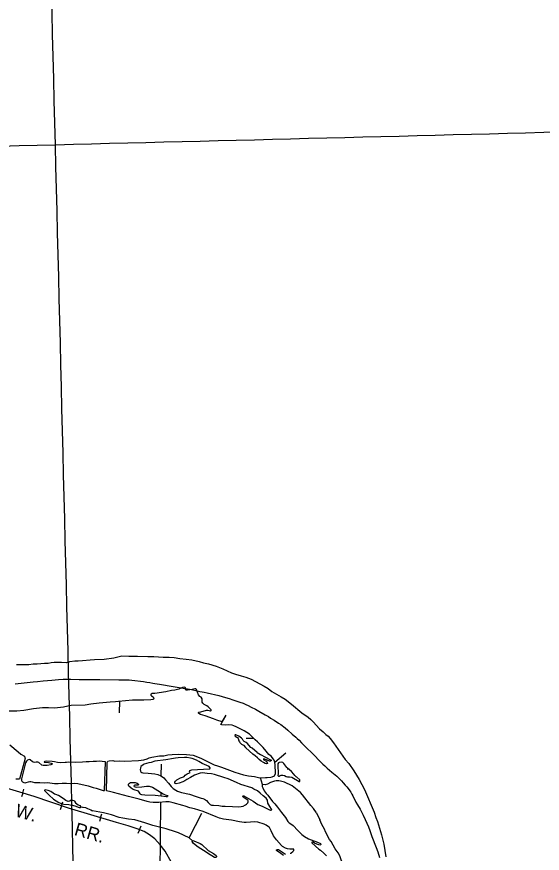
# Model space of a CAD drawing. Extents: x -19 to 366, y -4 to 359.
# Drawn here: x 141.56 to 144.78, y 204.19 to 209.31 of the extents above; entities that cross this region are included whole.
import ezdxf

# ---------------------------------------------------------------- set-up
doc = ezdxf.new("R2010")
doc.units = 0
for name, color, linetype in [('R_Alt Surface', 7, 'Continuous'), ('R_Axis Annot', 7, 'Continuous'), ('R_Border Prem', 7, 'Continuous'), ('R_Temp Easement', 7, 'Continuous'), ('R_Water Annot', 7, 'Continuous'), ('Sheet Fence', 7, 'Continuous')]:
    doc.layers.add(name, color=color, linetype=linetype)

msp = doc.modelspace()

# ---------------------------------------------------------------- linework, layer by layer
at = {"layer": 'R_Alt Surface'}
for points in [[(141.5515, 205.2236), (141.661, 205.2362), (141.6879, 205.2388), (141.7231, 205.242), (141.7768, 205.2467), (141.8179, 205.2499), (141.8458, 205.2525), (141.8589, 205.2525), (141.8926, 205.2523), (141.9431, 205.2504), (142.0193, 205.2496)], [(142.0193, 205.2496), (142.0693, 205.2496), (142.1869, 205.249), (142.2292, 205.2484), (142.2505, 205.2475), (142.2665, 205.246), (142.3385, 205.238), (142.3571, 205.2348), (142.3772, 205.2315), (142.3953, 205.2286), (142.4077, 205.2265), (142.4347, 205.2218), (142.5197, 205.2081), (142.5673, 205.1986), (142.6313, 205.1886), (142.6656, 205.1818), (142.6828, 205.1776), (142.6961, 205.1749), (142.7094, 205.1723), (142.7275, 205.1678), (142.7988, 205.1515), (142.8193, 205.1459), (142.8394, 205.1403), (142.8616, 205.1335), (142.8847, 205.1252), (142.9033, 205.1195), (142.927, 205.1115), (142.9475, 205.1047), (142.9652, 205.0976), (142.9791, 205.0917), (142.9975, 205.0819), (143.023, 205.0689), (143.0437, 205.0573), (143.0822, 205.0351), (143.1029, 205.0229), (143.1156, 205.0147), (143.1368, 205.0011), (143.1639, 204.9835), (143.1787, 204.974), (143.205, 204.9545), (143.2207, 204.9406), (143.2489, 204.9163), (143.2702, 204.8976), (143.2782, 204.8902), (143.2912, 204.8781), (143.306, 204.863), (143.3196, 204.8484), (143.3865, 204.7827), (143.412, 204.7569), (143.4241, 204.7444), (143.436, 204.732), (143.4475, 204.721), (143.4629, 204.7086), (143.4919, 204.6837), (143.5014, 204.6754), (143.5209, 204.6582), (143.5502, 204.6298), (143.5609, 204.6176), (143.5727, 204.604), (143.5822, 204.5933), (143.5908, 204.5833), (143.6015, 204.5699), (143.6077, 204.5599), (143.6136, 204.5495), (143.6189, 204.5376), (143.6388, 204.4994), (143.6485, 204.4828), (143.6642, 204.4562), (143.6826, 204.4203), (143.6941, 204.3945), (143.7045, 204.372), (143.7152, 204.3489), (143.724, 204.3261), (143.7368, 204.2897), (143.7619, 204.2212), (143.7717, 204.1949), (143.7829, 204.1608)]]:
    msp.add_lwpolyline(points, dxfattribs=at)
at = {"layer": 'R_Axis Annot'}
for points in [[(142.1899, 205.0458), (142.1925, 205.1185)], [(142.9669, 204.8907), (143.0126, 204.8917)], [(142.4463, 204.6598), (142.4472, 204.7328)], [(143.2202, 204.7076), (143.2202, 204.6985)], [(142.4449, 204.5364), (142.4451, 204.5585)], [(142.4392, 204.0642), (142.4444, 204.4985)]]:
    msp.add_lwpolyline(points, dxfattribs=at)
at = {"layer": 'R_Border Prem'}
for points in [[(141.8789, 205.3572), (141.8859, 205.3607), (141.9162, 205.3643), (141.9378, 205.3642), (141.9634, 205.3659), (142.0111, 205.3715), (142.0372, 205.3737), (142.0973, 205.3758), (142.1562, 205.3826), (142.2054, 205.3948), (142.2477, 205.3922), (142.2742, 205.3937), (142.3015, 205.3935), (142.3644, 205.391), (142.4, 205.391), (142.4577, 205.3879), (142.494, 205.3873), (142.5261, 205.3854), (142.5593, 205.3795), (142.5985, 205.3758), (142.6338, 205.3708), (142.6793, 205.3601), (142.7048, 205.3524), (142.7361, 205.3454), (142.7828, 205.3325), (142.8236, 205.316), (142.8768, 205.2912), (142.9011, 205.2824), (142.9351, 205.272), (142.9653, 205.2649), (142.9966, 205.2529), (143.0757, 205.21), (143.1012, 205.1944), (143.1237, 205.1774), (143.1811, 205.1444), (143.2049, 205.129), (143.2439, 205.1001), (143.3082, 205.0459), (143.3463, 205.0191), (143.3623, 205.0063), (143.3772, 204.9913), (143.4163, 204.9482), (143.4374, 204.9308), (143.4542, 204.9146), (143.469, 204.9027), (143.4814, 204.8887), (143.5017, 204.8628), (143.5733, 204.7613), (143.5945, 204.7368), (143.6249, 204.6923), (143.6582, 204.6387), (143.6911, 204.5771), (143.7494, 204.4383), (143.7608, 204.405), (143.7698, 204.3817), (143.7758, 204.3618), (143.7949, 204.3001), (143.8095, 204.2431), (143.8215, 204.1654)], [(141.8789, 205.3572), (141.8637, 205.3531), (141.836, 205.3546), (141.7914, 205.3548), (141.7725, 205.3527), (141.7543, 205.3487), (141.7317, 205.3483), (141.6864, 205.3445), (141.6627, 205.3436), (141.6363, 205.3403), (141.5607, 205.3392)], [(142.3832, 205.1601), (142.383, 205.1553), (142.3863, 205.1511), (142.3969, 205.1451), (142.4008, 205.137), (142.3995, 205.1309), (142.3957, 205.1278), (142.3832, 205.126), (142.3404, 205.1241), (142.2707, 205.1246), (142.1852, 205.115), (142.1671, 205.1128), (142.1332, 205.1122), (142.0667, 205.1052), (142.0157, 205.099), (141.9794, 205.0935), (141.8943, 205.0903), (141.875, 205.0879)], [(143.0364, 204.8679), (143.0219, 204.8802), (142.9996, 204.904), (142.9863, 204.9163), (142.9551, 204.9359), (142.9053, 204.9607), (142.8916, 204.9665), (142.88, 204.9701), (142.8592, 204.973), (142.8397, 204.9714), (142.8169, 204.9733), (142.8103, 204.9752), (142.82, 204.9918), (142.7859, 205.0007), (142.7657, 205.0092), (142.7152, 205.0275), (142.6866, 205.0359), (142.6759, 205.0415), (142.6744, 205.0448), (142.6744, 205.0474), (142.6757, 205.0499), (142.6884, 205.0521), (142.7228, 205.0624), (142.7321, 205.0628), (142.7486, 205.0577), (142.7507, 205.0583), (142.7518, 205.0602), (142.7518, 205.064), (142.7415, 205.0758), (142.7333, 205.0833), (142.7251, 205.089), (142.7084, 205.0974), (142.7002, 205.1054), (142.6975, 205.1115), (142.697, 205.1236), (142.6979, 205.1329), (142.6899, 205.1413), (142.6831, 205.1467), (142.6754, 205.1558), (142.6625, 205.1888), (142.6576, 205.1934), (142.6517, 205.1937), (142.6352, 205.1894), (142.6061, 205.1843), (142.5989, 205.1841), (142.596, 205.1856), (142.5947, 205.1886), (142.5952, 205.1959), (142.5941, 205.1993), (142.592, 205.2012), (142.5861, 205.2032), (142.5757, 205.202), (142.5543, 205.1914), (142.5299, 205.1847), (142.5093, 205.1828), (142.4737, 205.1741), (142.4078, 205.1655), (142.3894, 205.1639), (142.3858, 205.1627), (142.3832, 205.1601)], [(141.875, 205.0879), (141.8469, 205.0803), (141.7921, 205.0758), (141.7549, 205.0778), (141.72, 205.0762), (141.6634, 205.0701), (141.6058, 205.061), (141.5618, 205.0561), (141.5133, 205.0562)], [(142.8103, 204.9752), (142.8436, 205.0319)], [(142.82, 204.9918), (142.8436, 205.0319)], [(143.0345, 204.8031), (143.0039, 204.8293), (142.9953, 204.8348), (142.9726, 204.8607), (142.9663, 204.8652), (142.9532, 204.8707), (142.9477, 204.8771), (142.9442, 204.8843), (142.9385, 204.8921), (142.921, 204.9043), (142.9033, 204.9116), (142.8986, 204.9112), (142.8969, 204.9093), (142.8988, 204.904), (142.91, 204.8978), (142.9137, 204.8946), (142.9171, 204.8899), (142.9221, 204.8743), (142.9259, 204.8692), (142.9282, 204.8641), (142.9376, 204.8554), (142.949, 204.8482), (142.9629, 204.8344)], [(141.5197, 204.8506), (141.5708, 204.8078), (141.587, 204.7942), (141.6084, 204.7802), (141.6119, 204.7716), (141.6124, 204.767), (141.5788, 204.6413), (141.5553, 204.6411)], [(142.6496, 204.4594), (142.6217, 204.4659), (142.5921, 204.475), (142.5778, 204.4784), (142.5201, 204.4951), (142.4941, 204.5011), (142.4737, 204.5019), (142.4309, 204.4969), (142.3971, 204.4971), (142.3767, 204.4989), (142.3598, 204.5028), (142.3121, 204.5183), (142.2455, 204.5339), (142.1537, 204.5581), (142.1369, 204.5637), (142.1104, 204.5696), (142.1158, 204.7423), (142.1171, 204.7473), (142.1201, 204.7503), (142.1266, 204.7523), (142.1491, 204.7541), (142.1626, 204.7502), (142.1881, 204.7518), (142.2234, 204.75), (142.3064, 204.7548), (142.3397, 204.7582), (142.3601, 204.7642), (142.373, 204.77), (142.3877, 204.7743), (142.4358, 204.7823), (142.4624, 204.7834), (142.4875, 204.7887), (142.5137, 204.7917), (142.555, 204.7931), (142.6001, 204.7922), (142.6424, 204.7864), (142.6574, 204.7821), (142.6935, 204.7665), (142.7123, 204.7565), (142.7699, 204.7289), (142.7906, 204.721), (142.8147, 204.7145), (142.8652, 204.6949), (142.8969, 204.6838), (142.9491, 204.667), (142.981, 204.6598), (143.0164, 204.6558), (143.051, 204.6478), (143.0849, 204.6514), (143.0955, 204.6507), (143.1167, 204.6524), (143.1247, 204.6545), (143.1398, 204.6616), (143.1459, 204.6748), (143.1456, 204.6947), (143.1435, 204.7101), (143.143, 204.7269), (143.1421, 204.7447), (143.1379, 204.7559), (143.1325, 204.7644), (143.1209, 204.7785), (143.1055, 204.7922), (143.0971, 204.8025), (143.0883, 204.8114), (143.0698, 204.8346), (143.0364, 204.8679)], [(143.0345, 204.8031), (143.0532, 204.7916), (143.0857, 204.7752), (143.1104, 204.7613), (143.1165, 204.7587), (143.1188, 204.756), (143.1193, 204.7535), (143.1182, 204.7516), (143.1146, 204.7501), (143.1093, 204.7512), (143.0808, 204.7628), (143.0745, 204.7641), (143.0715, 204.7628), (143.0715, 204.7612), (143.0755, 204.7577), (143.0886, 204.7515), (143.0951, 204.7431), (143.0974, 204.7384), (143.0967, 204.7357), (143.0912, 204.734), (143.0829, 204.7356), (143.0716, 204.7417), (143.0572, 204.7515), (143.0467, 204.7605), (143.0362, 204.7713), (143.0219, 204.784), (143.0075, 204.7938), (142.9871, 204.8108), (142.9629, 204.8344)], [(143.1421, 204.7447), (143.2091, 204.8018)], [(141.8573, 204.7427), (141.8266, 204.741), (141.81, 204.7432), (141.7931, 204.7466), (141.7776, 204.749), (141.7412, 204.7501), (141.7331, 204.7487), (141.7288, 204.7459), (141.7296, 204.744), (141.7564, 204.742), (141.7732, 204.739), (141.7796, 204.7352), (141.7787, 204.7316), (141.771, 204.7281), (141.7477, 204.7244), (141.7223, 204.7236), (141.7144, 204.7263), (141.6971, 204.7425), (141.6906, 204.7452), (141.6809, 204.7437), (141.6721, 204.7421), (141.6633, 204.7434), (141.6587, 204.7457), (141.6432, 204.7592), (141.6382, 204.7603), (141.6269, 204.7572), (141.6214, 204.7503), (141.6149, 204.7403), (141.5905, 204.6426), (141.5914, 204.6317), (141.5924, 204.6287), (141.5975, 204.6232), (141.6048, 204.62), (141.6155, 204.6189), (141.6198, 204.6196), (141.6335, 204.6246), (141.6423, 204.6266), (141.6486, 204.6258), (141.6557, 204.6234), (141.6692, 204.6205), (141.7035, 204.62), (141.7343, 204.6185), (141.7507, 204.6195), (141.7918, 204.6148), (141.8152, 204.6132), (141.8405, 204.6157), (141.8655, 204.616), (141.8893, 204.6133), (141.9172, 204.6149)], [(141.9172, 204.6149), (141.9348, 204.6145), (141.999, 204.5996), (142.0303, 204.5893), (142.0474, 204.5845), (142.0605, 204.5819), (142.0916, 204.5709), (142.0977, 204.5705), (142.0986, 204.5709), (142.1059, 204.7457), (142.0841, 204.7475), (142.0688, 204.7498), (142.0494, 204.7486), (142.0288, 204.7485), (142.0044, 204.747), (141.9867, 204.7471), (141.9644, 204.7449), (141.9183, 204.7429), (141.8759, 204.744), (141.8655, 204.7426), (141.8573, 204.7427)], [(142.4735, 204.758), (142.4068, 204.7502), (142.3836, 204.7415), (142.3707, 204.7396), (142.3414, 204.7318), (142.3346, 204.7285), (142.3223, 204.7176), (142.3184, 204.7081), (142.3175, 204.6992), (142.3185, 204.6889), (142.3208, 204.6847), (142.3273, 204.681), (142.3345, 204.6791), (142.3671, 204.6772), (142.4063, 204.6734), (142.4263, 204.668), (142.4441, 204.6607), (142.455, 204.6543), (142.4628, 204.6475), (142.4721, 204.6361), (142.4914, 204.6155), (142.5067, 204.5962), (142.5194, 204.5839), (142.5348, 204.573), (142.5463, 204.5662), (142.5704, 204.5587), (142.6185, 204.5495), (142.6598, 204.534)], [(142.5369, 204.6127), (142.5316, 204.6142), (142.5287, 204.6163), (142.5291, 204.6214), (142.534, 204.6279), (142.5424, 204.6354), (142.5643, 204.6488), (142.5834, 204.6548), (142.5872, 204.6575), (142.5938, 204.6657), (142.6042, 204.673), (142.6202, 204.6798), (142.6229, 204.6817), (142.6212, 204.686), (142.6193, 204.6876), (142.6192, 204.69), (142.6221, 204.6933), (142.633, 204.697), (142.7403, 204.7031), (142.7446, 204.7044), (142.7461, 204.7075), (142.7463, 204.7092), (142.7447, 204.7122), (142.7394, 204.717), (142.6978, 204.7369), (142.6773, 204.7489), (142.6628, 204.7559), (142.6355, 204.7664), (142.625, 204.7694), (142.6023, 204.7726), (142.5894, 204.773), (142.5507, 204.7708), (142.5346, 204.7688), (142.5214, 204.7659), (142.4735, 204.758)], [(143.2195, 204.7081), (143.2147, 204.7117), (143.1971, 204.7371), (143.1899, 204.742), (143.1821, 204.7434), (143.1687, 204.7428), (143.1647, 204.7399), (143.1608, 204.7332), (143.1599, 204.7193), (143.163, 204.6781), (143.1617, 204.6724), (143.161, 204.6627), (143.1652, 204.6589), (143.1692, 204.6595), (143.1737, 204.6624), (143.1813, 204.6655), (143.1915, 204.665), (143.2006, 204.6618), (143.2105, 204.6569), (143.2188, 204.6547), (143.2325, 204.654)], [(143.2325, 204.654), (143.2456, 204.652), (143.2906, 204.6258), (143.2935, 204.6254), (143.2946, 204.6269), (143.2944, 204.6353), (143.2768, 204.6529), (143.2719, 204.6551), (143.2639, 204.6625), (143.2587, 204.6707), (143.2444, 204.6867), (143.2195, 204.7081)], [(142.6598, 204.534), (142.6898, 204.5233), (142.7019, 204.5215), (142.7118, 204.5171), (142.7232, 204.5102), (142.7333, 204.4983), (142.7457, 204.4856), (142.7539, 204.4813), (142.7662, 204.4804), (142.7982, 204.4796), (142.8191, 204.4742), (142.8382, 204.4755), (142.8826, 204.4731), (142.9194, 204.4719), (142.9366, 204.473), (142.948, 204.4759), (142.9631, 204.4828), (142.9693, 204.4872), (142.9768, 204.4964), (142.9793, 204.5008), (142.9794, 204.5086), (142.9771, 204.5122), (142.9486, 204.5305), (142.9451, 204.5339), (142.9451, 204.5365), (142.9472, 204.5386), (142.9521, 204.5392), (143.0101, 204.5052), (143.0368, 204.4861), (143.0641, 204.475), (143.1099, 204.4521), (143.1152, 204.4508), (143.1196, 204.4514), (143.1226, 204.455), (143.1224, 204.4575), (143.1115, 204.4723), (143.0991, 204.4941), (143.0971, 204.5114), (143.0898, 204.5235), (143.071, 204.5382), (143.0525, 204.5548), (143.035, 204.5682), (143.0139, 204.5795), (143.0005, 204.588), (142.9333, 204.6087), (142.9069, 204.6192), (142.8551, 204.6419), (142.8298, 204.6513), (142.773, 204.6685), (142.755, 204.6724), (142.7275, 204.6756), (142.6987, 204.6781), (142.6845, 204.6765), (142.6507, 204.664), (142.6263, 204.65), (142.6034, 204.638), (142.59, 204.6294), (142.5789, 204.6238), (142.5562, 204.6151), (142.5369, 204.6127)], [(143.066, 204.6083), (143.054, 204.6478)], [(142.3463, 204.5434), (142.3275, 204.5452), (142.3216, 204.5471), (142.3182, 204.5507), (142.3119, 204.5613), (142.3063, 204.5664), (142.2999, 204.5692), (142.2862, 204.5723), (142.2705, 204.5793), (142.2594, 204.587), (142.2482, 204.5972), (142.2461, 204.6022), (142.2466, 204.6105), (142.2511, 204.6163), (142.2575, 204.6195), (142.2657, 204.6205), (142.2856, 204.6199), (142.2987, 204.616), (142.3053, 204.6114), (142.3072, 204.6084), (142.3065, 204.6063), (142.3023, 204.6038), (142.2853, 204.6028), (142.2802, 204.601), (142.2785, 204.5987), (142.2812, 204.5953), (142.2857, 204.5936), (142.2946, 204.5922), (142.3274, 204.5939), (142.3556, 204.598), (142.3651, 204.5983), (142.3727, 204.597), (142.3934, 204.5904), (142.4255, 204.5701), (142.4586, 204.5505), (142.4702, 204.5449), (142.4843, 204.5398), (142.4864, 204.5374), (142.4856, 204.5351), (142.4833, 204.5328), (142.4769, 204.5318), (142.445, 204.5364), (142.4092, 204.5396)], [(143.3962, 204.4341), (143.3792, 204.4616), (143.3627, 204.4794), (143.311, 204.5441), (143.2984, 204.5578), (143.2485, 204.5995), (143.2006, 204.6228), (143.1764, 204.6286), (143.1669, 204.6298), (143.1504, 204.6297), (143.1398, 204.6278), (143.115, 204.6202), (143.0978, 204.6097), (143.0827, 204.6065), (143.066, 204.6083), (143.0651, 204.6059), (143.0649, 204.596), (143.0678, 204.5874), (143.0757, 204.5687), (143.0887, 204.5518), (143.098, 204.5418), (143.1276, 204.5037), (143.1415, 204.489), (143.1591, 204.468), (143.1826, 204.4369), (143.207, 204.4065), (143.2218, 204.3807), (143.2292, 204.3725), (143.2402, 204.3665), (143.2547, 204.3563), (143.2824, 204.3266), (143.3073, 204.3009), (143.3243, 204.2887), (143.3478, 204.2757), (143.4025, 204.2551), (143.4212, 204.2457), (143.4233, 204.2424), (143.4231, 204.2396), (143.4214, 204.2381), (143.4167, 204.2369), (143.4, 204.2423), (143.3855, 204.2493), (143.3766, 204.2557), (143.3696, 204.2562), (143.3679, 204.2534), (143.3692, 204.2499), (143.4109, 204.2129), (143.421, 204.2057), (143.4429, 204.187), (143.4574, 204.1711)], [(142.4092, 204.5396), (142.3463, 204.5434)], [(143.2398, 204.1838), (143.2398, 204.1882), (143.2411, 204.1899), (143.2522, 204.197), (143.2577, 204.2029), (143.2586, 204.2088), (143.2578, 204.2109), (143.2548, 204.2124), (143.2504, 204.2129), (143.2328, 204.2119), (143.219, 204.2149), (143.2081, 204.2182), (143.1893, 204.2284), (143.1826, 204.2348), (143.1519, 204.27), (143.1328, 204.2935), (143.1202, 204.325), (143.109, 204.3445), (143.1041, 204.3496), (143.0894, 204.3581), (143.0758, 204.3641), (143.037, 204.3772), (143.0192, 204.379), (142.9666, 204.3745), (142.9548, 204.3742), (142.9248, 204.3786), (142.8768, 204.3884), (142.8268, 204.3961), (142.8036, 204.4019), (142.7822, 204.4088), (142.7027, 204.4433), (142.6496, 204.4594)], [(143.3962, 204.4341), (143.4175, 204.3922)], [(143.5487, 204.0492), (143.568, 204.0246), (143.5712, 204.022), (143.5743, 204.0226), (143.5771, 204.0266), (143.5772, 204.0359), (143.5747, 204.0482), (143.561, 204.0879), (143.5584, 204.1118), (143.5516, 204.1367), (143.5476, 204.1462), (143.5402, 204.1703), (143.5289, 204.1898), (143.5116, 204.2139), (143.4863, 204.2582), (143.4775, 204.2718), (143.4526, 204.3177), (143.4462, 204.3333), (143.4307, 204.3621), (143.4175, 204.3922)], [(143.1953, 204.1729), (143.1713, 204.1923), (143.155, 204.201), (143.1529, 204.204), (143.1531, 204.2073), (143.1587, 204.2101), (143.1642, 204.2092), (143.2067, 204.1809)]]:
    msp.add_lwpolyline(points, dxfattribs=at)
at = {"layer": 'R_Temp Easement'}
for points in [[(141.9029, 204.5118), (141.8955, 204.5112), (141.8875, 204.506), (141.8762, 204.5038), (141.8629, 204.5095), (141.8449, 204.5211), (141.8172, 204.5405), (141.8005, 204.5473), (141.7926, 204.5495), (141.7849, 204.5538), (141.7694, 204.5647), (141.7535, 204.5701), (141.7357, 204.5751), (141.7323, 204.5739), (141.7314, 204.5704), (141.7473, 204.5555), (141.7601, 204.5415), (141.7873, 204.5182), (141.8199, 204.4972), (141.8389, 204.4898), (141.85, 204.4873), (141.8798, 204.4849), (141.8967, 204.4807)], [(141.9029, 204.5118), (141.9104, 204.5097), (141.916, 204.5052), (141.922, 204.4951), (141.9383, 204.4825), (141.947, 204.4786), (141.9513, 204.4736), (141.9524, 204.471), (141.9517, 204.4668), (141.9499, 204.4648), (141.9459, 204.4647), (141.9183, 204.4745), (141.8967, 204.4807)], [(141.9524, 204.471), (141.9633, 204.4682), (141.969, 204.4682), (141.9823, 204.4663), (141.9944, 204.4612), (142.0155, 204.4529), (142.026, 204.447)], [(142.6176, 204.2809), (142.5522, 204.3114), (142.5335, 204.3184), (142.4757, 204.3364), (142.3954, 204.3568), (142.3704, 204.3658), (142.3461, 204.3724), (142.325, 204.3796), (142.285, 204.3905), (142.2448, 204.3965), (142.212, 204.4007), (142.1888, 204.4049), (142.1421, 204.4229), (142.092, 204.4345), (142.026, 204.447)], [(142.6368, 204.2636), (142.6176, 204.2809), (142.6956, 204.4318)], [(142.7654, 204.1846), (142.7828, 204.1727), (142.7855, 204.1669), (142.7828, 204.1614), (142.7779, 204.1599), (142.7715, 204.1608), (142.756, 204.1702), (142.7455, 204.1781), (142.7049, 204.2031), (142.6733, 204.2237), (142.6437, 204.2472), (142.6356, 204.2581), (142.6352, 204.259), (142.6368, 204.2636), (142.6398, 204.2647), (142.6459, 204.2633), (142.6841, 204.247), (142.6957, 204.24), (142.7341, 204.2037)], [(142.7341, 204.2037), (142.7654, 204.1846)]]:
    msp.add_lwpolyline(points, dxfattribs=at)
at = {"layer": 'R_Water Annot'}
for p, q in [((141.5982, 204.5553), (141.5908, 204.5315)), ((141.5982, 204.5553), (141.6056, 204.5792)), ((141.8356, 204.4772), (141.8436, 204.5009)), ((141.8356, 204.4772), (141.8276, 204.4535)), ((142.0748, 204.4044), (142.0676, 204.3804)), ((142.0748, 204.4044), (142.0819, 204.4283)), ((142.3135, 204.3308), (142.3233, 204.3538)), ((142.3135, 204.3308), (142.3038, 204.3077))]:
    msp.add_line(p, q, dxfattribs=at)
for points in [[(142.5099, 204.1309), (142.4708, 204.1997), (142.4401, 204.2388), (142.4063, 204.2748), (142.3735, 204.3001), (142.3408, 204.3192), (142.2985, 204.3372), (142.2435, 204.3551), (142.1727, 204.3752), (141.8778, 204.463), (141.6674, 204.5339), (141.473, 204.5942), (141.084, 204.7052), (140.8145, 204.7792), (140.6749, 204.8226)], [(142.5099, 204.1309), (142.4708, 204.1997), (142.4401, 204.2388), (142.4063, 204.2748), (142.3735, 204.3001), (142.3408, 204.3192), (142.2985, 204.3372), (142.2435, 204.3551), (142.1727, 204.3752), (141.8778, 204.463), (141.6674, 204.5339), (141.473, 204.5942)]]:
    msp.add_lwpolyline(points, dxfattribs=at)
at = {"layer": 'Sheet Fence'}
for points in [[(146.7783, 1.697), (146.5788, 10.3131), (146.3785, 18.9294), (146.1776, 27.5458), (145.9759, 36.1624), (145.7736, 44.7791), (145.5705, 53.396), (145.3668, 62.013), (145.1624, 70.6301), (144.9572, 79.2474), (144.7514, 87.8648), (144.5449, 96.4823), (144.3377, 105.1), (144.1299, 113.7179), (143.9213, 122.3359), (143.712, 130.954), (143.5021, 139.5723), (143.2915, 148.1907), (143.0802, 156.8092), (142.8682, 165.4279), (142.6555, 174.0468), (142.4422, 182.6658), (142.2282, 191.2849), (142.0135, 199.9042), (141.7981, 208.5236), (141.582, 217.1432), (141.3653, 225.7629), (141.1479, 234.3828), (140.9298, 243.0028), (140.711, 251.623), (140.4916, 260.2433), (140.2715, 268.8638), (140.0508, 277.4844), (139.8293, 286.1051), (139.6072, 294.726), (139.3845, 303.3471), (139.161, 311.9683), (138.937, 320.5896), (138.7122, 329.2111), (138.4868, 337.8328), (138.2607, 346.4546)], [(0, 206.7492), (7.0906, 206.7536), (14.1813, 206.7669), (21.2719, 206.7891), (28.3625, 206.8201), (35.453, 206.8601), (42.5435, 206.9089), (49.6339, 206.9665), (56.7242, 207.0331), (63.8144, 207.1085), (70.9046, 207.1928), (77.9946, 207.286), (85.0845, 207.388), (92.1743, 207.4989), (99.2639, 207.6187), (106.3534, 207.7473), (113.4427, 207.8849), (120.5319, 208.0312), (127.6208, 208.1865), (134.7095, 208.3506), (141.7981, 208.5236), (148.8864, 208.7055), (155.9745, 208.8963), (163.0623, 209.0959), (170.1499, 209.3044), (177.2372, 209.5217), (184.3242, 209.7479), (191.411, 209.983), (198.4974, 210.227), (205.5835, 210.4798), (212.6694, 210.7415), (219.7548, 211.012), (226.84, 211.2915), (233.9248, 211.5798), (241.0092, 211.8769), (248.0932, 212.1829), (255.1768, 212.4978), (262.2601, 212.8216), (269.3429, 213.1542), (276.4254, 213.4956), (283.5073, 213.846), (290.5889, 214.2052), (297.67, 214.5732), (304.7506, 214.9502), (311.8307, 215.3359), (318.9104, 215.7306), (325.9895, 216.1341), (333.0682, 216.5464), (340.1463, 216.9676)], [(0, 198.1326), (7.1014, 198.137), (14.2028, 198.1503), (21.3042, 198.1724), (28.4055, 198.2034), (35.5068, 198.2433), (42.6081, 198.292), (49.7092, 198.3496), (56.8103, 198.4161), (63.9113, 198.4913), (71.0123, 198.5755), (78.1131, 198.6685), (85.2137, 198.7704), (92.3143, 198.8811), (99.4147, 199.0007), (106.5149, 199.1291), (113.615, 199.2664), (120.7149, 199.4126), (127.8146, 199.5676), (134.9141, 199.7315), (142.0135, 199.9042), (149.1125, 200.0858), (156.2114, 200.2762), (163.31, 200.4755), (170.4084, 200.6837), (177.5065, 200.9007), (184.6043, 201.1265), (191.7018, 201.3612), (198.799, 201.6048), (205.896, 201.8572), (212.9926, 202.1185), (220.0888, 202.3886), (227.1848, 202.6676), (234.2803, 202.9554), (241.3755, 203.2521), (248.4704, 203.5576), (255.5648, 203.872), (262.6589, 204.1952), (269.7525, 204.5273), (276.8457, 204.8682), (283.9385, 205.218), (291.0309, 205.5766), (298.1228, 205.9441), (305.2142, 206.3204), (312.3051, 206.7056), (319.3956, 207.0996), (326.4856, 207.5024), (333.5751, 207.9141), (340.664, 208.3347)]]:
    msp.add_spline(points, degree=3, dxfattribs=at)

# ---------------------------------------------------------------- texts
at = {"layer": 'R_Water Annot'}
for s, p in [('W.', (141.5462, 204.4139)), ('RR.', (141.9088, 204.2997))]:
    msp.add_text(s, height=0.08, rotation=343.9823, dxfattribs=at).set_placement(p)

doc.saveas('drawing.dxf')
